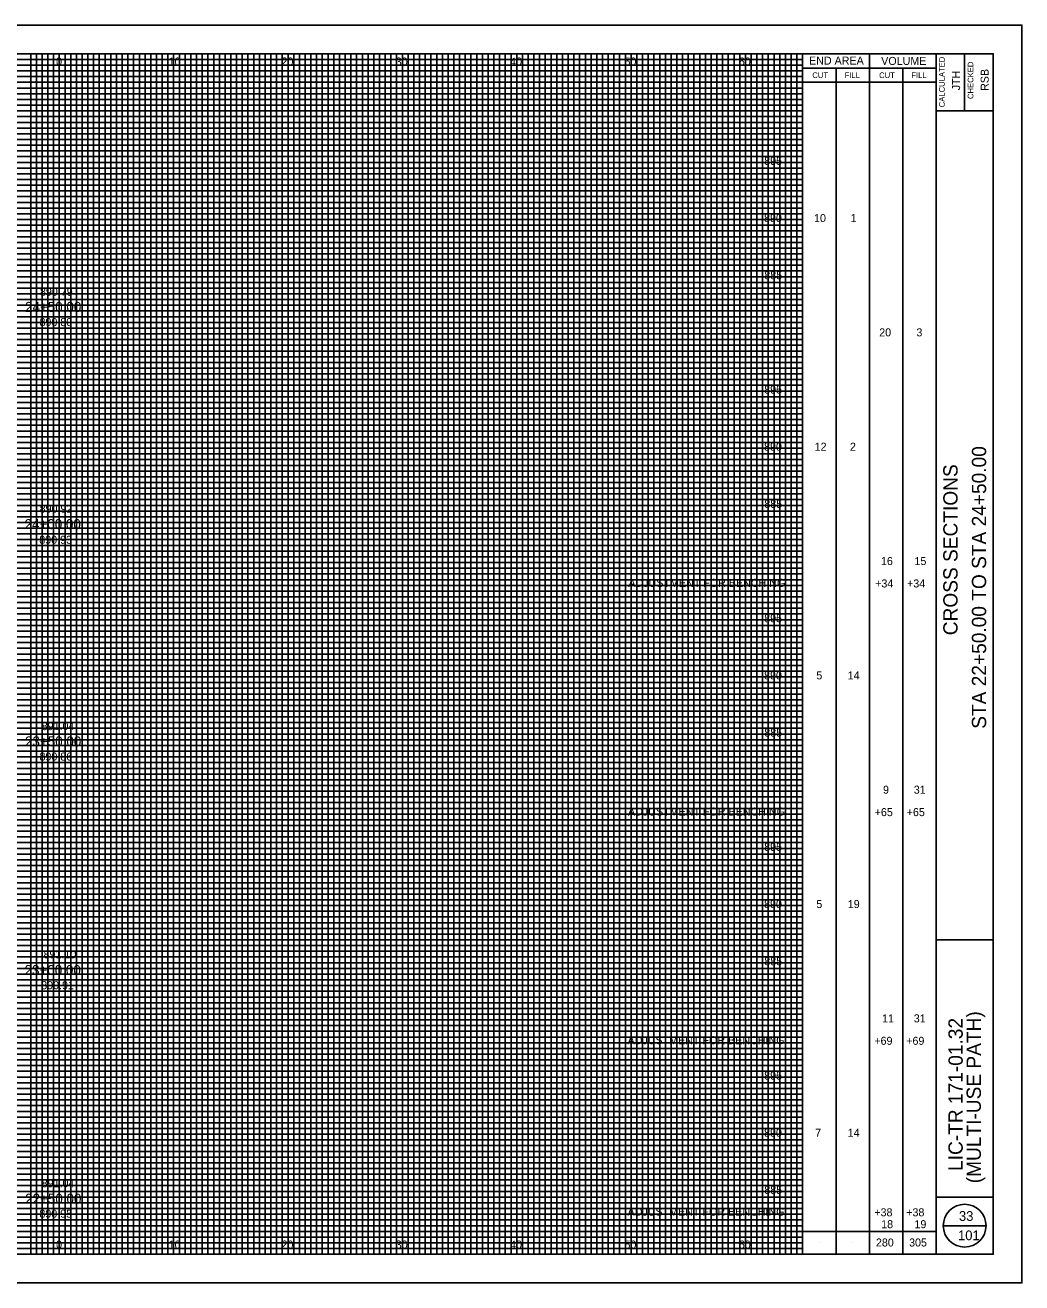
# Model space of a CAD drawing. Extents: x -10 to 160, y -2 to 2522.
# Drawn here: x 72.8 to 160, y 572.5 to 682.5 of the extents above; entities that cross this region are included whole.
import ezdxf

# ---------------------------------------------------------------- set-up
doc = ezdxf.new("R2010")
doc.units = 0
for name, color, linetype in [('GK_Cells', 7, 'Continuous'), ('GK_Patterns', 7, 'Continuous'), ('TX_P_10', 7, 'Continuous'), ('TX_X_10', 7, 'Continuous'), ('XS_P_Finished_Grade_Seeded', 7, 'Continuous'), ('XS_P_Pavt_Surface', 7, 'Continuous'), ('XS_P_Subgrade', 7, 'Continuous'), ('XS_X_Ground_Line', 7, 'Continuous')]:
    doc.layers.add(name, color=color, linetype=linetype)

msp = doc.modelspace()

# ---------------------------------------------------------------- linework, layer by layer
at = {"layer": 'GK_Cells'}
msp.add_lwpolyline([(-10, 572.5), (160, 572.5), (160, 682.5), (-10, 682.5)], close=True, dxfattribs=at)
at = {"layer": 'TX_P_10'}
for p, q in [((140.83, 575), (140.83, 680)), ((146.67, 575), (146.67, 680)), ((140.83, 678.75), (152.5, 678.75)), ((143.75, 575), (143.75, 678.75)), ((149.58, 575), (149.58, 678.75)), ((140.83, 677.5), (152.5, 677.5)), ((153.12, 577.5), (156.88, 577.5)), ((140.83, 577), (152.5, 577)), ((142.29, 576), (142.29, 576)), ((145.21, 576), (145.21, 576)), ((148.12, 576), (148.12, 576)), ((151.04, 576), (151.04, 576))]:
    msp.add_line(p, q, dxfattribs=at)
msp.add_circle((155, 577.5), 1.87, dxfattribs=at)
at = {"layer": 'TX_X_10'}
for p, q in [((75.83, 575), (75.83, 680)), ((80.83, 575), (80.83, 680)), ((85.83, 575), (85.83, 680)), ((90.83, 575), (90.83, 680)), ((95.83, 575), (95.83, 680)), ((100.83, 575), (100.83, 680)), ((105.83, 575), (105.83, 680)), ((110.83, 575), (110.83, 680)), ((115.83, 575), (115.83, 680)), ((120.83, 575), (120.83, 680)), ((125.83, 575), (125.83, 680)), ((130.83, 575), (130.83, 680)), ((135.83, 575), (135.83, 680)), ((5.83, 675), (140.83, 675)), ((5.83, 670), (140.83, 670)), ((5.83, 665), (140.83, 665)), ((5.83, 660), (140.83, 660)), ((5.83, 655), (140.83, 655)), ((5.83, 650), (140.83, 650)), ((5.83, 645), (140.83, 645)), ((5.83, 640), (140.83, 640)), ((5.83, 635), (140.83, 635)), ((5.83, 630), (140.83, 630)), ((5.83, 625), (140.83, 625)), ((5.83, 620), (140.83, 620)), ((5.83, 615), (140.83, 615)), ((5.83, 610), (140.83, 610)), ((5.83, 605), (140.83, 605)), ((5.83, 600), (140.83, 600)), ((5.83, 595), (140.83, 595)), ((5.83, 590), (140.83, 590)), ((5.83, 585), (140.83, 585)), ((5.83, 580), (140.83, 580))]:
    msp.add_line(p, q, dxfattribs=at)
at = {"layer": 'XS_P_Pavt_Surface'}
for p, q in [((152.5, 575), (152.5, 680)), ((155, 680), (155, 675)), ((152.5, 675), (157.5, 675)), ((152.5, 602.5), (157.5, 602.5)), ((152.5, 580), (157.5, 580))]:
    msp.add_line(p, q, dxfattribs=at)
msp.add_lwpolyline([(0, 680), (157.5, 680), (157.5, 575), (0, 575)], close=True, dxfattribs=at)
at = {"layer": 'XS_X_Ground_Line'}
for p, q in [((73.33, 575), (73.33, 680)), ((73.83, 575), (73.83, 680)), ((74.33, 575), (74.33, 680)), ((74.83, 575), (74.83, 680)), ((75.33, 575), (75.33, 680)), ((76.33, 575), (76.33, 680)), ((76.83, 575), (76.83, 680)), ((77.33, 575), (77.33, 680)), ((77.83, 575), (77.83, 680)), ((78.33, 575), (78.33, 680)), ((78.83, 575), (78.83, 680)), ((79.33, 575), (79.33, 680)), ((79.83, 575), (79.83, 680)), ((80.33, 575), (80.33, 680)), ((81.33, 575), (81.33, 680)), ((81.83, 575), (81.83, 680)), ((82.33, 575), (82.33, 680)), ((82.83, 575), (82.83, 680)), ((83.33, 575), (83.33, 680)), ((83.83, 575), (83.83, 680)), ((84.33, 575), (84.33, 680)), ((84.83, 575), (84.83, 680)), ((85.33, 575), (85.33, 680)), ((86.33, 575), (86.33, 680)), ((86.83, 575), (86.83, 680)), ((87.33, 575), (87.33, 680)), ((87.83, 575), (87.83, 680)), ((88.33, 575), (88.33, 680)), ((88.83, 575), (88.83, 680)), ((89.33, 575), (89.33, 680)), ((89.83, 575), (89.83, 680)), ((90.33, 575), (90.33, 680)), ((91.33, 575), (91.33, 680)), ((91.83, 575), (91.83, 680)), ((92.33, 575), (92.33, 680)), ((92.83, 575), (92.83, 680)), ((93.33, 575), (93.33, 680)), ((93.83, 575), (93.83, 680)), ((94.33, 575), (94.33, 680)), ((94.83, 575), (94.83, 680)), ((95.33, 575), (95.33, 680)), ((96.33, 575), (96.33, 680)), ((96.83, 575), (96.83, 680)), ((97.33, 575), (97.33, 680)), ((97.83, 575), (97.83, 680)), ((98.33, 575), (98.33, 680)), ((98.83, 575), (98.83, 680)), ((99.33, 575), (99.33, 680)), ((99.83, 575), (99.83, 680)), ((100.33, 575), (100.33, 680)), ((101.33, 575), (101.33, 680)), ((101.83, 575), (101.83, 680)), ((102.33, 575), (102.33, 680)), ((102.83, 575), (102.83, 680)), ((103.33, 575), (103.33, 680)), ((103.83, 575), (103.83, 680)), ((104.33, 575), (104.33, 680)), ((104.83, 575), (104.83, 680)), ((105.33, 575), (105.33, 680)), ((106.33, 575), (106.33, 680)), ((106.83, 575), (106.83, 680)), ((107.33, 575), (107.33, 680)), ((107.83, 575), (107.83, 680)), ((108.33, 575), (108.33, 680)), ((108.83, 575), (108.83, 680)), ((109.33, 575), (109.33, 680)), ((109.83, 575), (109.83, 680)), ((110.33, 575), (110.33, 680)), ((111.33, 575), (111.33, 680)), ((111.83, 575), (111.83, 680)), ((112.33, 575), (112.33, 680)), ((112.83, 575), (112.83, 680)), ((113.33, 575), (113.33, 680)), ((113.83, 575), (113.83, 680)), ((114.33, 575), (114.33, 680)), ((114.83, 575), (114.83, 680)), ((115.33, 575), (115.33, 680)), ((116.33, 575), (116.33, 680)), ((116.83, 575), (116.83, 680)), ((117.33, 575), (117.33, 680)), ((117.83, 575), (117.83, 680)), ((118.33, 575), (118.33, 680)), ((118.83, 575), (118.83, 680)), ((119.33, 575), (119.33, 680)), ((119.83, 575), (119.83, 680)), ((120.33, 575), (120.33, 680)), ((121.33, 575), (121.33, 680)), ((121.83, 575), (121.83, 680)), ((122.33, 575), (122.33, 680)), ((122.83, 575), (122.83, 680)), ((123.33, 575), (123.33, 680)), ((123.83, 575), (123.83, 680)), ((124.33, 575), (124.33, 680)), ((124.83, 575), (124.83, 680)), ((125.33, 575), (125.33, 680)), ((126.33, 575), (126.33, 680)), ((126.83, 575), (126.83, 680)), ((127.33, 575), (127.33, 680)), ((127.83, 575), (127.83, 680)), ((128.33, 575), (128.33, 680)), ((128.83, 575), (128.83, 680)), ((129.33, 575), (129.33, 680)), ((129.83, 575), (129.83, 680)), ((130.33, 575), (130.33, 680)), ((131.33, 575), (131.33, 680)), ((131.83, 575), (131.83, 680)), ((132.33, 575), (132.33, 680)), ((132.83, 575), (132.83, 680)), ((133.33, 575), (133.33, 680)), ((133.83, 575), (133.83, 680)), ((134.33, 575), (134.33, 680)), ((134.83, 575), (134.83, 680)), ((135.33, 575), (135.33, 680)), ((136.33, 575), (136.33, 680)), ((136.83, 575), (136.83, 680)), ((137.33, 575), (137.33, 680)), ((137.83, 575), (137.83, 680)), ((138.33, 575), (138.33, 680)), ((138.83, 575), (138.83, 680)), ((139.33, 575), (139.33, 680)), ((139.83, 575), (139.83, 680)), ((140.33, 575), (140.33, 680)), ((5.83, 679.5), (140.83, 679.5)), ((5.83, 679), (140.83, 679)), ((5.83, 678.5), (140.83, 678.5)), ((5.83, 678), (140.83, 678)), ((5.83, 677.5), (140.83, 677.5)), ((5.83, 677), (140.83, 677)), ((5.83, 676.5), (140.83, 676.5)), ((5.83, 676), (140.83, 676)), ((5.83, 675.5), (140.83, 675.5)), ((5.83, 674.5), (140.83, 674.5)), ((5.83, 674), (140.83, 674)), ((5.83, 673.5), (140.83, 673.5)), ((5.83, 673), (140.83, 673)), ((5.83, 672.5), (140.83, 672.5)), ((5.83, 672), (140.83, 672)), ((5.83, 671.5), (140.83, 671.5)), ((5.83, 671), (140.83, 671)), ((5.83, 670.5), (140.83, 670.5)), ((5.83, 669.5), (140.83, 669.5)), ((5.83, 669), (140.83, 669)), ((5.83, 668.5), (140.83, 668.5)), ((5.83, 668), (140.83, 668)), ((5.83, 667.5), (140.83, 667.5)), ((5.83, 667), (140.83, 667)), ((5.83, 666.5), (140.83, 666.5)), ((5.83, 666), (140.83, 666)), ((5.83, 665.5), (140.83, 665.5)), ((5.83, 664.5), (140.83, 664.5)), ((5.83, 664), (140.83, 664)), ((5.83, 663.5), (140.83, 663.5)), ((5.83, 663), (140.83, 663)), ((5.83, 662.5), (140.83, 662.5)), ((5.83, 662), (140.83, 662)), ((5.83, 661.5), (140.83, 661.5)), ((5.83, 661), (140.83, 661)), ((5.83, 660.5), (140.83, 660.5)), ((5.83, 659.5), (140.83, 659.5)), ((5.83, 659), (140.83, 659)), ((5.83, 658.5), (140.83, 658.5)), ((5.83, 658), (140.83, 658)), ((5.83, 657.5), (140.83, 657.5)), ((5.83, 657), (140.83, 657)), ((5.83, 656.5), (140.83, 656.5)), ((5.83, 656), (140.83, 656)), ((5.83, 655.5), (140.83, 655.5)), ((5.83, 654.5), (140.83, 654.5)), ((5.83, 654), (140.83, 654)), ((5.83, 653.5), (140.83, 653.5)), ((5.83, 653), (140.83, 653)), ((5.83, 652.5), (140.83, 652.5)), ((5.83, 652), (140.83, 652)), ((5.83, 651.5), (140.83, 651.5)), ((5.83, 651), (140.83, 651)), ((5.83, 650.5), (140.83, 650.5)), ((5.83, 649.5), (140.83, 649.5)), ((5.83, 649), (140.83, 649)), ((5.83, 648.5), (140.83, 648.5)), ((5.83, 648), (140.83, 648)), ((5.83, 647.5), (140.83, 647.5)), ((5.83, 647), (140.83, 647)), ((5.83, 646.5), (140.83, 646.5)), ((5.83, 646), (140.83, 646)), ((5.83, 645.5), (140.83, 645.5)), ((5.83, 644.5), (140.83, 644.5)), ((5.83, 644), (140.83, 644)), ((5.83, 643.5), (140.83, 643.5)), ((5.83, 643), (140.83, 643)), ((5.83, 642.5), (140.83, 642.5)), ((5.83, 642), (140.83, 642)), ((5.83, 641.5), (140.83, 641.5)), ((5.83, 641), (140.83, 641)), ((5.83, 640.5), (140.83, 640.5)), ((5.83, 639.5), (140.83, 639.5)), ((5.83, 639), (140.83, 639)), ((5.83, 638.5), (140.83, 638.5)), ((5.83, 638), (140.83, 638)), ((5.83, 637.5), (140.83, 637.5)), ((5.83, 637), (140.83, 637)), ((5.83, 636.5), (140.83, 636.5)), ((5.83, 636), (140.83, 636)), ((5.83, 635.5), (140.83, 635.5)), ((5.83, 634.5), (140.83, 634.5)), ((5.83, 634), (140.83, 634)), ((5.83, 633.5), (140.83, 633.5)), ((5.83, 633), (140.83, 633)), ((5.83, 632.5), (140.83, 632.5)), ((5.83, 632), (140.83, 632)), ((5.83, 631.5), (140.83, 631.5)), ((5.83, 631), (140.83, 631)), ((5.83, 630.5), (140.83, 630.5)), ((5.83, 629.5), (140.83, 629.5)), ((5.83, 629), (140.83, 629)), ((5.83, 628.5), (140.83, 628.5)), ((5.83, 628), (140.83, 628)), ((5.83, 627.5), (140.83, 627.5)), ((5.83, 627), (140.83, 627)), ((5.83, 626.5), (140.83, 626.5)), ((5.83, 626), (140.83, 626)), ((5.83, 625.5), (140.83, 625.5)), ((5.83, 624.5), (140.83, 624.5)), ((5.83, 624), (140.83, 624)), ((5.83, 623.5), (140.83, 623.5)), ((5.83, 623), (140.83, 623)), ((5.83, 622.5), (140.83, 622.5)), ((5.83, 622), (140.83, 622)), ((5.83, 621.5), (140.83, 621.5)), ((5.83, 621), (140.83, 621)), ((5.83, 620.5), (140.83, 620.5)), ((5.83, 619.5), (140.83, 619.5)), ((5.83, 619), (140.83, 619)), ((5.83, 618.5), (140.83, 618.5)), ((5.83, 618), (140.83, 618)), ((5.83, 617.5), (140.83, 617.5)), ((5.83, 617), (140.83, 617)), ((5.83, 616.5), (140.83, 616.5)), ((5.83, 616), (140.83, 616)), ((5.83, 615.5), (140.83, 615.5)), ((5.83, 614.5), (140.83, 614.5)), ((5.83, 614), (140.83, 614)), ((5.83, 613.5), (140.83, 613.5)), ((5.83, 613), (140.83, 613)), ((5.83, 612.5), (140.83, 612.5)), ((5.83, 612), (140.83, 612)), ((5.83, 611.5), (140.83, 611.5)), ((5.83, 611), (140.83, 611)), ((5.83, 610.5), (140.83, 610.5)), ((5.83, 609.5), (140.83, 609.5)), ((5.83, 609), (140.83, 609)), ((5.83, 608.5), (140.83, 608.5)), ((5.83, 608), (140.83, 608)), ((5.83, 607.5), (140.83, 607.5)), ((5.83, 607), (140.83, 607)), ((5.83, 606.5), (140.83, 606.5)), ((5.83, 606), (140.83, 606)), ((5.83, 605.5), (140.83, 605.5)), ((5.83, 604.5), (140.83, 604.5)), ((5.83, 604), (140.83, 604)), ((5.83, 603.5), (140.83, 603.5)), ((5.83, 603), (140.83, 603)), ((5.83, 602.5), (140.83, 602.5)), ((5.83, 602), (140.83, 602)), ((5.83, 601.5), (140.83, 601.5)), ((5.83, 601), (140.83, 601)), ((5.83, 600.5), (140.83, 600.5)), ((5.83, 599.5), (140.83, 599.5)), ((5.83, 599), (140.83, 599)), ((5.83, 598.5), (140.83, 598.5)), ((5.83, 598), (140.83, 598)), ((5.83, 597.5), (140.83, 597.5)), ((5.83, 597), (140.83, 597)), ((5.83, 596.5), (140.83, 596.5)), ((5.83, 596), (140.83, 596)), ((5.83, 595.5), (140.83, 595.5)), ((5.83, 594.5), (140.83, 594.5)), ((5.83, 594), (140.83, 594)), ((5.83, 593.5), (140.83, 593.5)), ((5.83, 593), (140.83, 593)), ((5.83, 592.5), (140.83, 592.5)), ((5.83, 592), (140.83, 592)), ((5.83, 591.5), (140.83, 591.5)), ((5.83, 591), (140.83, 591)), ((5.83, 590.5), (140.83, 590.5)), ((5.83, 589.5), (140.83, 589.5)), ((5.83, 589), (140.83, 589)), ((5.83, 588.5), (140.83, 588.5)), ((5.83, 588), (140.83, 588)), ((5.83, 587.5), (140.83, 587.5)), ((5.83, 587), (140.83, 587)), ((5.83, 586.5), (140.83, 586.5)), ((5.83, 586), (140.83, 586)), ((5.83, 585.5), (140.83, 585.5)), ((5.83, 584.5), (140.83, 584.5)), ((5.83, 584), (140.83, 584)), ((5.83, 583.5), (140.83, 583.5)), ((5.83, 583), (140.83, 583)), ((5.83, 582.5), (140.83, 582.5)), ((5.83, 582), (140.83, 582)), ((5.83, 581.5), (140.83, 581.5)), ((5.83, 581), (140.83, 581)), ((5.83, 580.5), (140.83, 580.5)), ((5.83, 579.5), (140.83, 579.5)), ((5.83, 579), (140.83, 579)), ((5.83, 578.5), (140.83, 578.5)), ((5.83, 578), (140.83, 578)), ((5.83, 577.5), (140.83, 577.5)), ((5.83, 577), (140.83, 577)), ((5.83, 576.5), (140.83, 576.5)), ((5.83, 576), (140.83, 576)), ((5.83, 575.5), (140.83, 575.5))]:
    msp.add_line(p, q, dxfattribs=at)

# ---------------------------------------------------------------- texts
at = {"layer": 'GK_Patterns'}
for s, height, p in [('0', 0.7, (75.55, 678.97)), ('0', 0.7, (75.55, 678.97)), ('10', 0.7, (85.39, 678.97)), ('20', 0.7, (95.26, 678.97)), ('30', 0.7, (105.25, 678.97)), ('40', 0.7, (115.25, 678.97)), ('50', 0.7, (125.25, 678.97)), ('60', 0.7, (135.25, 678.97)), ('895', 0.7, (137.47, 670.28)), ('890', 0.7, (137.46, 665.28)), ('10', 0.7, (141.83, 665.28)), ('1', 0.7, (145.03, 665.28)), ('885', 0.7, (137.48, 660.28)), ('24+50.00', 0.875, (72.84, 657.42)), ('20', 0.7, (147.53, 655.28)), ('3', 0.7, (150.78, 655.28)), ('895', 0.7, (137.47, 650.28)), ('890', 0.7, (137.46, 645.28)), ('12', 0.7, (141.88, 645.28)), ('2', 0.7, (144.97, 645.28)), ('885', 0.7, (137.48, 640.28)), ('24+00.00', 0.875, (72.8, 638.42)), ('16', 0.7, (147.68, 635.28)), ('15', 0.7, (150.61, 635.28)), ('ADJUSTMENT FOR BENCHING', 0.7, (125.59, 633.37)), ('+34', 0.7, (147.17, 633.32)), ('+34', 0.7, (149.96, 633.32)), ('895', 0.7, (137.47, 630.28)), ('890', 0.7, (137.46, 625.28)), ('5', 0.7, (142.03, 625.28)), ('14', 0.7, (144.77, 625.28)), ('885', 0.7, (137.48, 620.28)), ('23+50.00', 0.875, (72.84, 619.42)), ('9', 0.7, (147.86, 615.28)), ('31', 0.7, (150.55, 615.28)), ('ADJUSTMENT FOR BENCHING', 0.7, (125.56, 613.37)), ('+65', 0.7, (147.13, 613.32)), ('+65', 0.7, (149.93, 613.32)), ('895', 0.7, (137.47, 610.28)), ('890', 0.7, (137.46, 605.28)), ('5', 0.7, (142.03, 605.28)), ('19', 0.7, (144.78, 605.28)), ('885', 0.7, (137.48, 600.28)), ('23+00.00', 0.875, (72.8, 599.42)), ('11', 0.7, (147.78, 595.28)), ('31', 0.7, (150.55, 595.28)), ('ADJUSTMENT FOR BENCHING', 0.7, (125.52, 593.37)), ('+69', 0.7, (147.1, 593.32)), ('+69', 0.7, (149.89, 593.32)), ('895', 0.7, (137.47, 590.28)), ('890', 0.7, (137.46, 585.28)), ('7', 0.7, (141.93, 585.28)), ('14', 0.7, (144.77, 585.28)), ('885', 0.7, (137.48, 580.28)), ('22+50.00', 0.875, (72.85, 579.42)), ('ADJUSTMENT FOR BENCHING', 0.7, (125.52, 578.37)), ('+38', 0.7, (147.1, 578.32)), ('+38', 0.7, (149.89, 578.32)), ('18', 0.7, (147.7, 577.28)), ('19', 0.7, (150.61, 577.28)), ('0', 0.7, (75.55, 575.5)), ('0', 0.7, (75.55, 575.5)), ('10', 0.7, (85.39, 575.5)), ('20', 0.7, (95.26, 575.5)), ('30', 0.7, (105.25, 575.5)), ('40', 0.7, (115.25, 575.5)), ('50', 0.7, (125.25, 575.5)), ('60', 0.7, (135.25, 575.5)), ('280', 0.7, (147.24, 575.68)), ('305', 0.7, (150.14, 575.68))]:
    msp.add_text(s, height=height, dxfattribs=at).set_placement(p)
at = {"layer": 'TX_P_10'}
for s, height, p in [('END AREA', 0.7, (141.39, 679.05)), ('VOLUME', 0.7, (147.7, 679.02)), ('CUT', 0.5, (141.68, 677.87)), ('FILL', 0.5, (144.5, 677.87)), ('CUT', 0.5, (147.52, 677.87)), ('FILL', 0.5, (150.34, 677.87)), ('33', 0.85, (154.5, 577.92)), ('101', 0.85, (154.42, 576.23))]:
    msp.add_text(s, height=height, dxfattribs=at).set_placement(p)
for s, height, p in [('CALCULATED', 0.5, (153.26, 675.32)), ('CHECKED', 0.5, (155.76, 676.04)), ('JTH', 0.7, (154.6, 676.8)), ('RSB', 0.7, (157.1, 676.75)), ('STA 22+50.00 TO STA 24+50.00', 1.25, (156.88, 620.96)), ('CROSS SECTIONS', 1.25, (154.38, 629.14)), ('LIC-TR 171-01.32', 1.25, (154.83, 582.29)), ('(MULTI-USE PATH)', 1.25, (156.42, 581.21))]:
    msp.add_text(s, height=height, rotation=90, dxfattribs=at).set_placement(p)
at = {"layer": 'XS_P_Finished_Grade_Seeded'}
for s, p in [('890.80', (74.1, 656.18)), ('890.93', (74.08, 637.14)), ('890.86', (74.1, 618.18)), ('890.91', (74.25, 598.18)), ('890.95', (74.09, 578.2))]:
    msp.add_text(s, height=0.7, dxfattribs=at).set_placement(p)
at = {"layer": 'XS_P_Subgrade'}
for s, p in [('890.79', (74.14, 658.83)), ('890.92', (74.11, 639.86)), ('891.04', (74.29, 620.84)), ('891.10', (74.45, 600.88)), ('891.04', (74.29, 580.86))]:
    msp.add_text(s, height=0.7, dxfattribs=at).set_placement(p)

doc.saveas('drawing.dxf')
